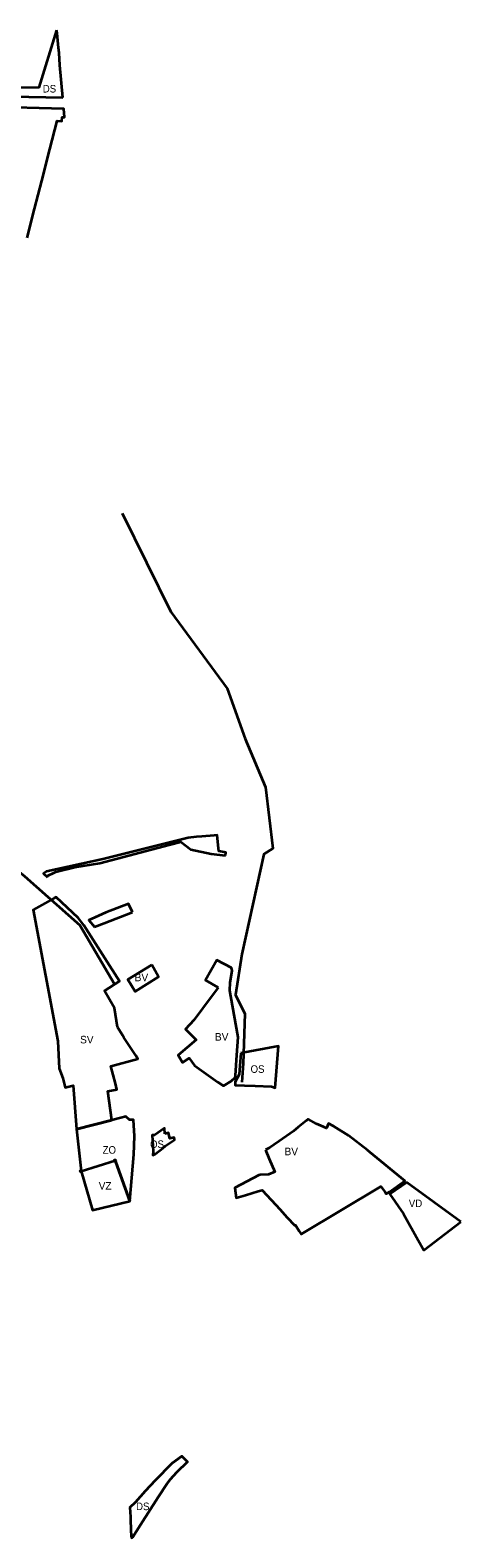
# Model space of a CAD drawing. Extents: x -650276 to -642489, y -1074311 to -1066658.
# Drawn here: x -645218 to -644537, y -1073665 to -1071277 of the extents above; entities that cross this region are included whole.
import ezdxf

# ---------------------------------------------------------------- set-up
doc = ezdxf.new("R2010")
doc.units = 0
doc.header["$LTSCALE"] = 4.8
doc.header["$PDMODE"] = 32
doc.header["$PDSIZE"] = 2.4
for name, color, linetype, lineweight in [('15', 7, 'Continuous', 35), ('18', 7, 'Continuous', 35), ('24', 7, 'Continuous', 35), ('3', 7, 'Continuous', 35), ('35', 7, 'Continuous', 35), ('36', 7, 'Continuous', 35), ('42', 7, 'Continuous', 35), ('54', 7, 'Continuous', 35), ('9', 7, 'Continuous', 35)]:
    doc.layers.add(name, color=color, linetype=linetype, lineweight=lineweight)
doc.layers.add('62', color=7, linetype='Continuous')

msp = doc.modelspace()

# ---------------------------------------------------------------- linework, layer by layer
at = {"layer": '15'}
for points in [[(-644926.81, -1072552.51), (-644946.57, -1072554.22), (-644954.57, -1072554.43), (-644967.97, -1072556.17), (-644978.56, -1072558.74), (-644999.72, -1072564.24), (-645102.73, -1072589.74), (-645192.06, -1072609.19), (-645197.044, -1072612.821), (-645190.71, -1072618.6)], [(-644919.75, -1072572.43), (-644921.84, -1072552.03), (-644926.81, -1072552.51)], [(-645147.13, -1072602.79), (-645107.58, -1072596.47), (-644997.92, -1072567.23), (-644979.55, -1072562.44), (-644963.97, -1072574.57)], [(-644963.97, -1072574.57), (-644931.48, -1072581.26), (-644909.02, -1072584.28)], [(-644909.02, -1072584.28), (-644908.59, -1072579.51), (-644919.23, -1072577.46), (-644919.75, -1072572.43)], [(-645190.71, -1072618.6), (-645190.59, -1072616.28), (-645179.6, -1072610.94), (-645177.56, -1072609.89), (-645147.13, -1072602.79)], [(-645056.08, -1072674.07), (-645062.131, -1072660.856), (-645098.016, -1072674.425), (-645115.56, -1072682.406), (-645124.933, -1072686.721), (-645116.11, -1072697.15)], [(-645116.11, -1072697.15), (-645100.9, -1072691.31), (-645056.08, -1072674.07)]]:
    msp.add_lwpolyline(points, dxfattribs=at)
at = {"layer": '18'}
msp.add_lwpolyline([(-645144.37, -1073017.64), (-645088.62, -1073003.45), (-645095.04, -1072957.07), (-645080.61, -1072954.43), (-645083.13, -1072944.94), (-645090.34, -1072917.86), (-645047.42, -1072906.05), (-645050.6, -1072901.03), (-645069.55, -1072872.12), (-645071.87, -1072868.45), (-645079.81, -1072855.89), (-645084.47, -1072825.67), (-645100.27, -1072798.46), (-645076.66, -1072783.06), (-645099.58, -1072746.945), (-645121.96, -1072711.68), (-645133.26, -1072694.17), (-645142.1, -1072682.57), (-645176.757, -1072649.968), (-645180.05, -1072651.77), (-645213.34, -1072669.98), (-645174.13, -1072877.93), (-645172.28, -1072921.42), (-645166.48, -1072936.5), (-645162.379, -1072951.55), (-645149.84, -1072948.13)], close=True, dxfattribs=at)
at = {"layer": '24'}
for points in [[(-645176.14, -1071277.26), (-645204.341, -1071368.19), (-645348.55, -1071370.559), (-645388.619, -1071366.991), (-645539.738, -1071364.092), (-645642.431, -1071362.259), (-645650.28, -1071362.07), (-645674.947, -1071355.071), (-645684.785, -1071362.539), (-645677.58, -1071366.16), (-645643.56, -1071374.75), (-645497.84, -1071377.53), (-645327.76, -1071380.76), (-645166.34, -1071384.07)], [(-645166.34, -1071384.07), (-645170.91, -1071332.86), (-645172.03, -1071312.96), (-645172.85, -1071305.45), (-645175.4, -1071281.93), (-645175.67, -1071279.45), (-645176.14, -1071277.26)], [(-645222.48, -1071606.08), (-645211.27, -1071560.01), (-645199.61, -1071515.68), (-645186.67, -1071465.55), (-645175.06, -1071420.93), (-645167.58, -1071421.19), (-645167.37, -1071415.2), (-645163.56, -1071415.3), (-645164.76, -1071401.79), (-645281.92, -1071398.82)], [(-645060.009, -1073616.53), (-645051.513, -1073608.124), (-645035.303, -1073590.199), (-645020.11, -1073573.585), (-644993.044, -1073546.324), (-644977.924, -1073535.072), (-644969.117, -1073544.254), (-644985.66, -1073560.69), (-644996.41, -1073571.97), (-645001.267, -1073578.582), (-645015.55, -1073599.96), (-645043.35, -1073644.04), (-645056.06, -1073664.2)], [(-645056.06, -1073664.2), (-645043.35, -1073644.04), (-645015.55, -1073599.96), (-645001.267, -1073578.582), (-644996.41, -1073571.97), (-644985.66, -1073560.69), (-644969.117, -1073544.254), (-644977.924, -1073535.072), (-644993.044, -1073546.324), (-645020.11, -1073573.585), (-645035.303, -1073590.199), (-645051.513, -1073608.124), (-645060.009, -1073616.53)], [(-645060.009, -1073616.53), (-645059.35, -1073631.3), (-645058.96, -1073640.09), (-645058.65, -1073647), (-645058.42, -1073652.18), (-645058.01, -1073661.37), (-645057.87, -1073664.55), (-645056.06, -1073664.2)]]:
    msp.add_lwpolyline(points, dxfattribs=at)
at = {"layer": '3'}
for points in [[(-644902.18, -1072797.88), (-644901.35, -1072785.36), (-644898.29, -1072766.55), (-644899.2, -1072762.14), (-644922.88, -1072749.97), (-644940.8, -1072781.48), (-644920.46, -1072792.92)], [(-644920.46, -1072792.92), (-644945.2, -1072826.3), (-644959.24, -1072844.92), (-644972.28, -1072859.02), (-644955.49, -1072875.78), (-644983.93, -1072900.24), (-644977.16, -1072912.11), (-644966.57, -1072905.23), (-644957.79, -1072916.73), (-644921.18, -1072943.17), (-644911.87, -1072948.76), (-644900.2, -1072941.67), (-644893.77, -1072935.88), (-644892.86, -1072932.6), (-644891.2, -1072900.09), (-644889.11, -1072871.66), (-644895.32, -1072836.6), (-644902.18, -1072797.88)]]:
    msp.add_lwpolyline(points, dxfattribs=at)
for points in [[(-645025.61, -1072757.17), (-645063.6, -1072780.26), (-645051.94, -1072799.21), (-645015.02, -1072776.01)], [(-644845.72, -1073050.14), (-644839.57, -1073064.5), (-644830.81, -1073084.98), (-644840.89, -1073089.3), (-644853.8, -1073089.99), (-644856.4, -1073090.13), (-644894.15, -1073110.3), (-644892.14, -1073126.36), (-644877.32, -1073121.83), (-644856.97, -1073115.6), (-644851, -1073113.77), (-644822.62, -1073144.71), (-644811.96, -1073156.75), (-644799.26, -1073170.13), (-644798.38, -1073169.56), (-644792.59, -1073178.73), (-644789.31, -1073183.93), (-644663.17, -1073108.27), (-644656.56, -1073117.4), (-644654.61, -1073120.1), (-644649.7, -1073116.65), (-644625.26, -1073099.51), (-644680.69, -1073053.67), (-644684.09, -1073050.8), (-644714.42, -1073027.62), (-644714.42, -1073027.62), (-644737.88, -1073012.62), (-644745.73, -1073008.64), (-644748.95, -1073015.64), (-644757.73, -1073012.05), (-644764.69, -1073008.87), (-644778.38, -1073001.84), (-644781.52, -1073004.39), (-644793.743, -1073014.293), (-644801.54, -1073020.61), (-644824.08, -1073036.56), (-644832.7, -1073042.34), (-644839.47, -1073046.89)]]:
    msp.add_lwpolyline(points, close=True, dxfattribs=at)
at = {"layer": '35'}
for points in [[(-644536.62, -1073164.33), (-644622.03, -1073101.88), (-644630.58, -1073107.78), (-644648.95, -1073120.47), (-644627.53, -1073151.26)], [(-644627.53, -1073151.26), (-644604.13, -1073193), (-644595.18, -1073208.98), (-644536.62, -1073164.33)]]:
    msp.add_lwpolyline(points, dxfattribs=at)
at = {"layer": '36'}
msp.add_lwpolyline([(-645137.5, -1073083.97), (-645119.34, -1073145.61), (-645060.1, -1073131.68), (-645082.6, -1073069.93), (-645083.681, -1073066.962)], dxfattribs=at)
for p in [(-645137.5, -1073083.97), (-645083.681, -1073066.962)]:
    msp.add_point(p, dxfattribs=at)
at = {"layer": '42'}
msp.add_lwpolyline([(-645054.12, -1073057.62), (-645052.94, -1073028.58), (-645054.44, -1073002.54), (-645060.95, -1073002.68), (-645066.66, -1072997.3), (-645074.333, -1072999.365), (-645088.62, -1073003.45), (-645144.37, -1073017.64), (-645137.5, -1073083.97), (-645083.681, -1073066.962), (-645082.6, -1073069.93), (-645060.1, -1073131.68)], close=True, dxfattribs=at)
at = {"layer": '54'}
for points in [[(-646336.784, -1071524.232), (-646218.737, -1071612.767), (-646164.374, -1071674.897), (-645904.456, -1071961.331), (-645718.199, -1072151.712), (-645526.944, -1072343.922), (-645538, -1072384), (-645459, -1072440), (-645389, -1072483), (-645335, -1072526), (-645287, -1072569), (-645227, -1072617), (-645139.573, -1072694.628), (-645084.365, -1072788.086)], [(-645072.161, -1072041.834), (-644995.618, -1072198.247), (-644906.317, -1072319.547), (-644877.614, -1072399.349), (-644845.721, -1072475.959), (-644833.873, -1072573.126), (-644848.261, -1072581.918), (-644882.834, -1072740.552), (-644893.098, -1072804.559), (-644878.097, -1072834.588), (-644880.803, -1072913.277), (-644882.834, -1072942.847)]]:
    msp.add_lwpolyline(points, dxfattribs=at)
at = {"layer": '9'}
for points in [[(-644884.712, -1072897.147), (-644886.418, -1072916.953), (-644887.44, -1072930.94), (-644893.37, -1072942.61), (-644893.59, -1072947.97), (-644878.86, -1072948.42), (-644861.93, -1072948.94), (-644835.99, -1072949.74), (-644830.25, -1072951.9), (-644825.25, -1072885.96)], [(-645004.82, -1073024.63), (-645005.31, -1073015.68), (-645021.1, -1073026.69), (-645024.71, -1073026.95), (-645023.6, -1073052.12), (-645023.88, -1073058.37), (-645019.57, -1073056.46), (-645007.99, -1073047.31), (-645003.78, -1073043.96), (-644989.34, -1073034.58), (-644990.25, -1073030.54), (-644997.09, -1073032.21), (-644999.23, -1073023.29)]]:
    msp.add_lwpolyline(points, close=True, dxfattribs=at)

# ---------------------------------------------------------------- texts
at = {"layer": '62', "width": 0.95}
for s, p in [('DS', (-645198.003, -1071376.001)), ('OS', (-644869.265, -1072928.272)), ('OS', (-645028.265, -1073047.272)), ('ZO', (-645103.327, -1073056.309)), ('VD', (-644618.892, -1073140.939)), ('DS', (-645050.407, -1073620.717))]:
    msp.add_text(s, height=12, dxfattribs=at).set_placement(p)
at = {"layer": '62'}
for s, p in [('BV', (-645052.614, -1072783.26)), ('SV', (-645139.013, -1072881.667)), ('BV', (-644925.614, -1072877.26)), ('BV', (-644815.563, -1073058.759)), ('VZ', (-645109.496, -1073113.102))]:
    msp.add_text(s, height=12, dxfattribs=at).set_placement(p)

doc.saveas('drawing.dxf')
